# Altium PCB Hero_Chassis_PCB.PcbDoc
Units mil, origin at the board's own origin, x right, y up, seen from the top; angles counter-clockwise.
Board outline 2952.76 x 1771.65 mil, 2 copper layers (Top Layer, Bottom Layer); 15 components, 15 nets, 51 pads, 0 vias.
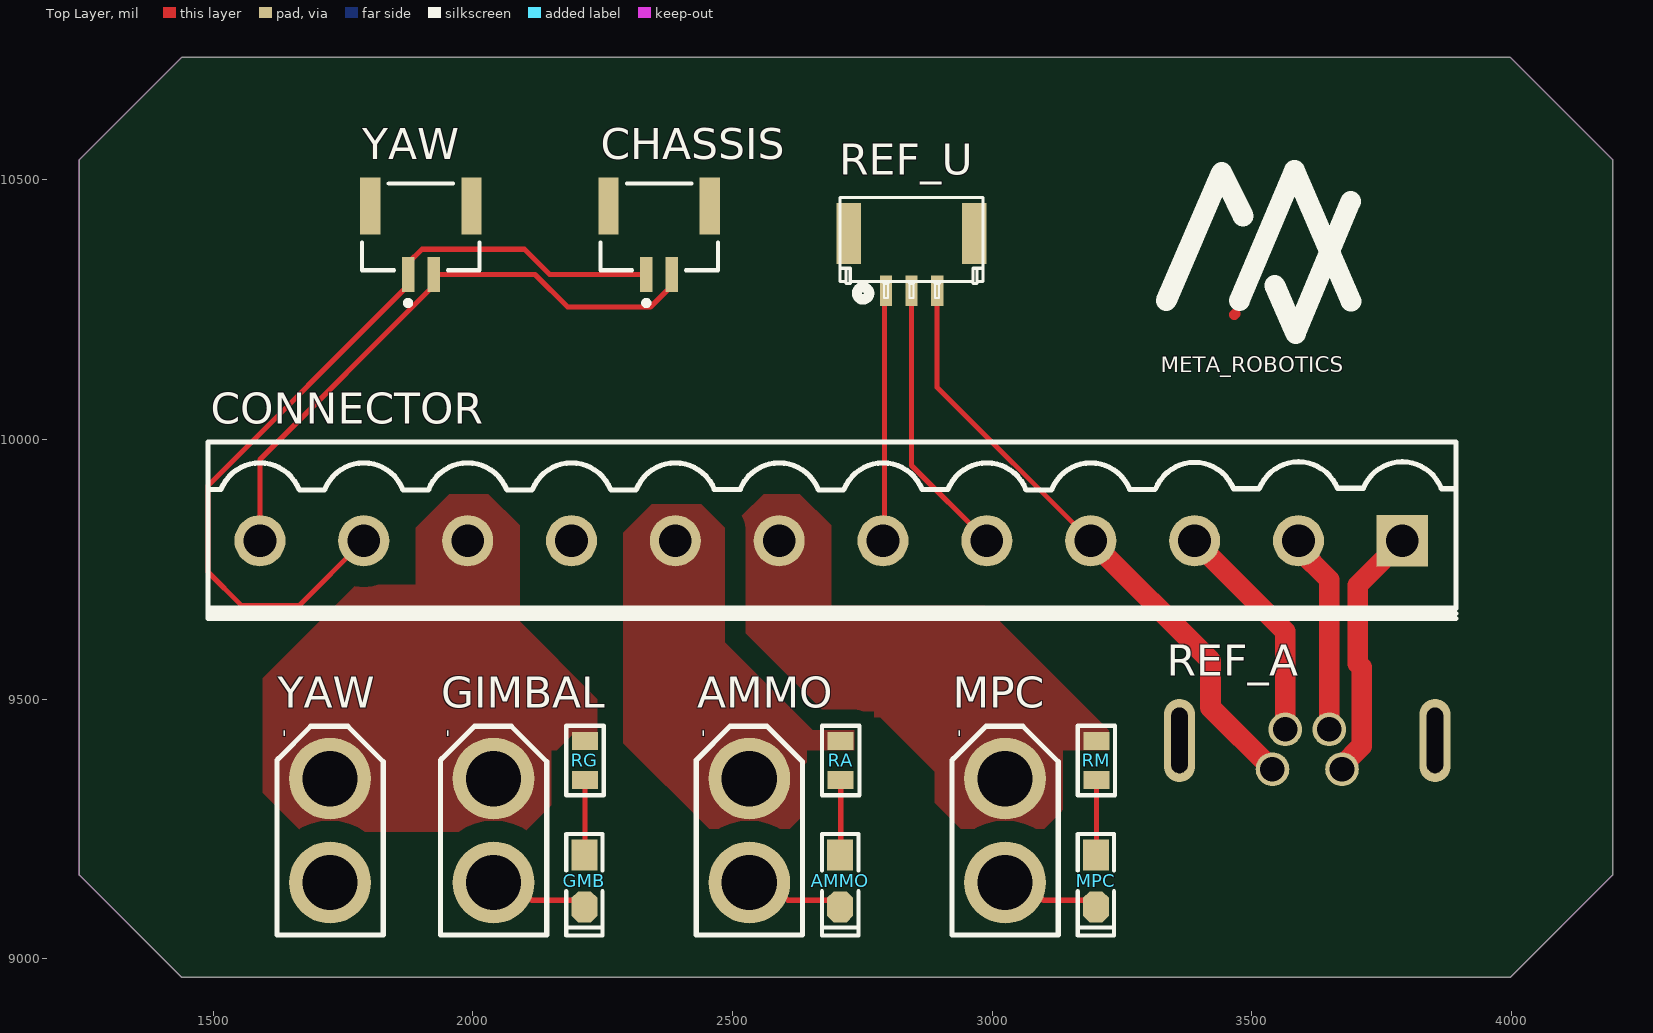
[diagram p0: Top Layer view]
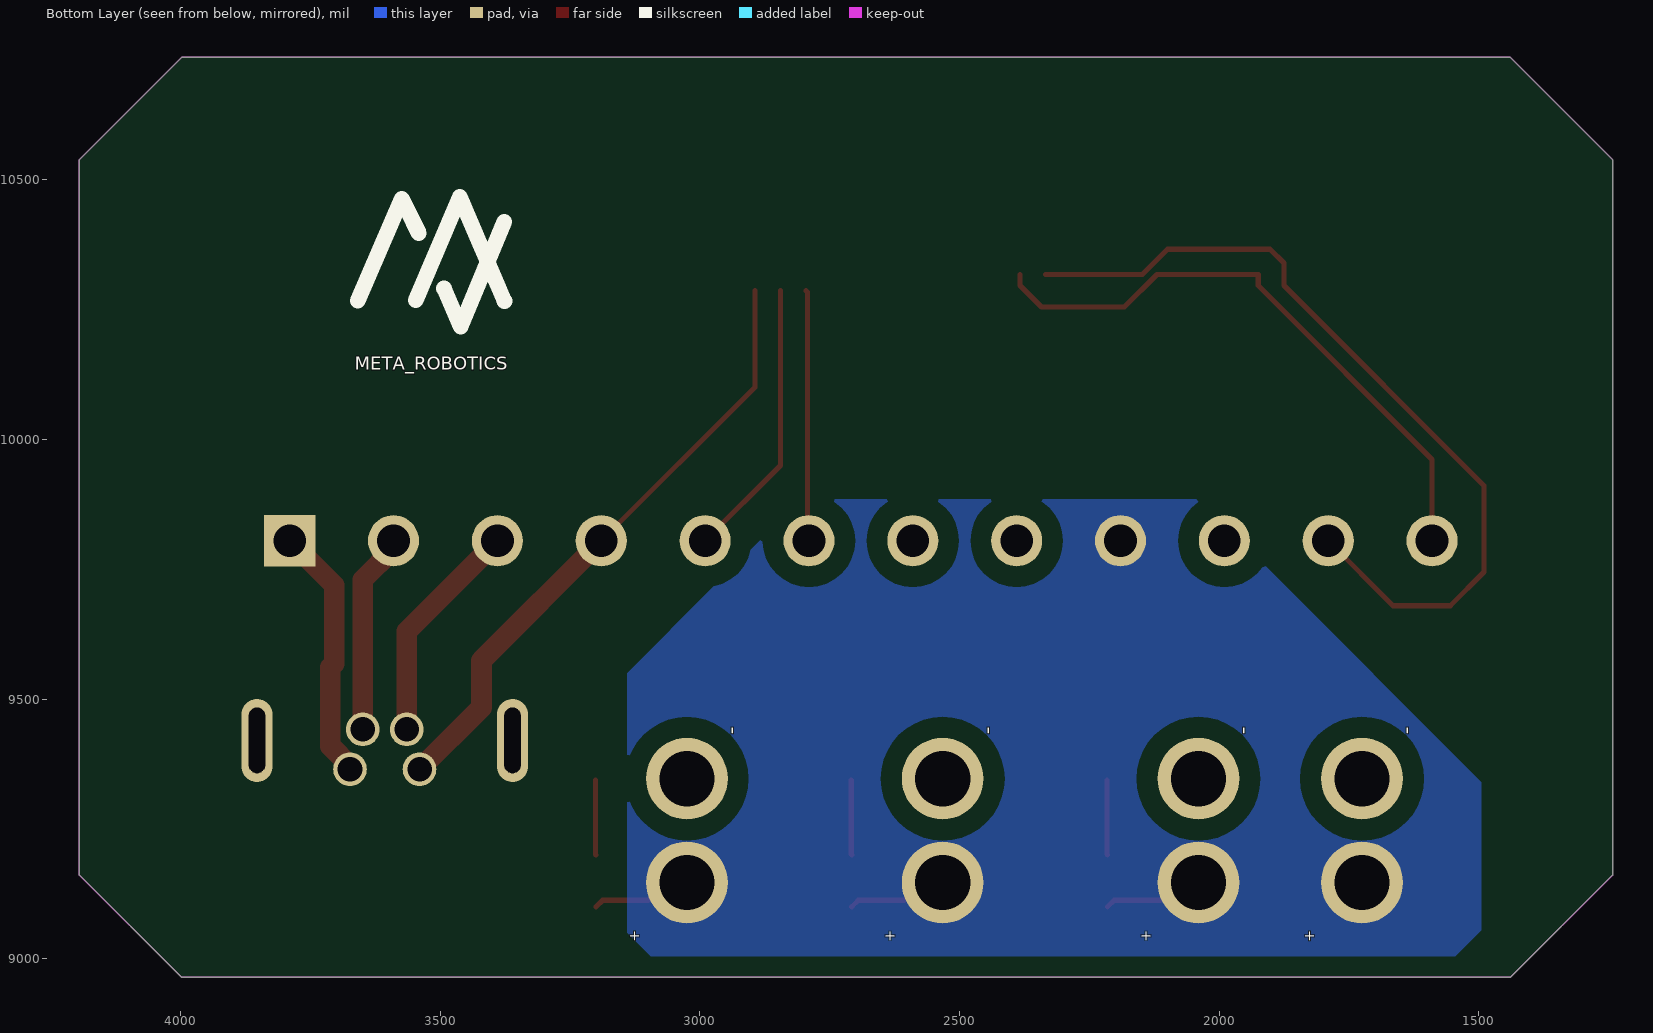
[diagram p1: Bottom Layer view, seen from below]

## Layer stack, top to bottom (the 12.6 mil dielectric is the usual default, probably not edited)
Top Solder: solder mask 0.4, Solder Resist, Dk 3.5
Top Layer: signal copper 1.4
Dielectric 1: dielectric 12.6, FR-4, Dk 4.8
Bottom Layer: signal copper 1.4
Bottom Solder: solder mask 0.4, Solder Resist, Dk 3.5

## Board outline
1439.14,8964.25 1242.29,9161.1 1242.29,10539.05 1439.14,10735.9 3998.19,10735.9 4195.04,10539.05 4195.04,9161.1 3998.19,8964.25

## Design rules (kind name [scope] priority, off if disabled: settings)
Clearance [InPolygon] p1: gap=40 ignorepadtopadclearanceinfootprint=FALSE
PlaneClearance [All] p1: clearance=40
PlaneConnect [All] p1: planeconnectstyle=Direct reliefexpansion=20 reliefentries=4 reliefconductorwidth=10 reliefairgap=10
PolygonConnect [All] p1: connectstyle=Direct reliefconductorwidth=10 reliefentries=4 polygonreliefangle="90 Angle" airgapwidth=10
RoutingVias [All] p1: holewidth=28 width=50 viastyle="Through Hole" minholewidth=28 minwidth=50 maxholewidth=28 maxwidth=50
SolderMaskExpansion [All] p1: expansion=4 istentingtop=FALSE
Width [All] p1: maxlimit=80 minlimit=10 preferedwidth=40
28 further rules are at their usual default settings.

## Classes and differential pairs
component class Schematic: AMMO CHASSIS CONNECTOR GIMBAL GMB MPC RA REF_A REF_U RG RM YAW

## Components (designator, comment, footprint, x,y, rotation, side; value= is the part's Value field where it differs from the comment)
AMMO "XT PLUGIN" XT30-M 2532.5,9246.79 r90 top
AMMO "红色" "LED 0805G" 2707.5,9150 r270 top
CHASSIS "CAN1" JST-BM02B-GHS-TBT_V 2358.72,10383.95 r0 top
CONNECTOR "HDR-1X12" KF2EDGK5.08-LI-12P 2690,9805 r180 top
GIMBAL "XT PLUGIN" XT30-M 2040,9246.79 r90 top
GMB "红色" "LED 0805G" 2215.01,9150 r270 top
MPC "XT PLUGIN" XT30-M 3024.99,9246.79 r90 top
MPC "红色" "LED 0805G" 3200,9150 r270 top
RA "10K" "R 0805_L" 2708.51,9381.86 r270 top
REF_A "Referee_Air" "M8 Connector" 3606.93,9402.4 r0 top
REF_U "gh1.25_3p" GH1.25-LS-3P 2845,10385 r180 top
RG "10K" "R 0805_L" 2216.01,9381.86 r270 top
RM "10K" "R 0805_L" 3201,9381.86 r270 top
YAW "CAN1" JST-BM02B-GHS-TBT_V 1900,10383.95 r0 top
YAW "XT PLUGIN" XT30-M 1725,9246.79 r90 top

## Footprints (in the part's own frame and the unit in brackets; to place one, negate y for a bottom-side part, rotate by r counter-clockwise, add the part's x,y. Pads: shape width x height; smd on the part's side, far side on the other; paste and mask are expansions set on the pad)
GH1.25-LS-3P [mm] "A1257WR-S-3P"
  rect 1.2x3 smd: 0(-3.075,-0.3) 0(3.075,-0.3)
  rect 0.6x1.5 smd: 1(1.25,2.5) 2(0,2.5) 3(-1.25,2.5)
  silkscreen extent -3.5,-2.05 3.5,2.93, body extent -3.5,-2.15 3.5,2.25, height 4.2
JST-BM02B-GHS-TBT_V [mm] "Connector, 2-Leads, Body 5.75x4.25mm, Pitch 1.25mm"
  rect 0.6x1.7 smd: 1(-0.625,-1.675) 2(0.625,-1.675)
  rect 1x2.8 smd: MP1(-2.475,1.675) MP2(2.475,1.675)
  silkscreen extent -2.88,-3.2 2.88,2.78, body extent -2.88,-2.17 2.87,2.78, height 4.21
KF2EDGK5.08-LI-12P [mm] "立插端子"
  rect 2.5x2.5 hole 1.6: 1(-27.94,0)
  round 2.5 hole 1.6: 2(-22.86,0) 3(-17.78,0) 4(-12.7,0) 5(-7.62,0) 6(-2.54,0) 7(2.54,0) 8(7.62,0) 9(12.7,0) 10(17.78,0) 11(22.86,0) 12(27.94,0)
  silkscreen extent -30.56,-4.83 30.48,3.81, body extent -30.48,-4.75 30.48,3.75, height 11.25
"LED 0805G" [mil] "绿色0805LED                              淘宝ID:黄晶宝石"
  rect 60x50 smd: 1(-50,0)
  oct 60x50 smd: 2(50,0)
  silkscreen extent -90,-35 105,35, body extent -39,-25 39,25, height 32
"M8 Connector" [mm]
  round 1.65 hole 1.2: 0(-1.075,1) 1(1.075,1) 2(-1.7,-0.95) 3(1.7,-0.95)
  oval 1.524x4.064 hole 0.8 slot 3.2 at 90 deg: 4(-6.25,0.46) 5(6.25,0.46)
  body extent -6.25,-19.34 6.25,1.96, height 11.3
"R 0805_L" [mil] "1/8W贴片电阻"
  rect 35x50 smd: 1(-37.4,0) 2(37.4,0)
  silkscreen extent -67,-36 67,36, body extent -39,-25 39,25, height 20
XT30-M [mm]
  round 4 hole 2.7: 1(-2.54,0) 2(2.54,0)
  silkscreen extent -5.1,-2.6 5.11,2.6, body extent -5.18,-2.8 5.02,2.8, height 10.66

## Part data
AMMO GMB MPC: library part LED-SMD, "贴片LED"
CHASSIS YAW: library part CMP-2000-05957-1, "Disconnectable Crimp Style Connector, Pitch 1.25 mm, 1 x 2 Position, Height 4.05 mm, -25 to 85 degC, RoHS, Tape and Reel", Color=Natural, Manufacturer=JST-Sales-America-Inc., Package Description="Disconnectable Crimp Style Connector, Pitch 1.25 mm, 1 x 2 Position, Height 4.05 mm", Package Reference=BM02B-GHS-TBT
CONNECTOR: library part "Header 12", "12P接插件"
RA RG RM: library part R, "贴片电阻"

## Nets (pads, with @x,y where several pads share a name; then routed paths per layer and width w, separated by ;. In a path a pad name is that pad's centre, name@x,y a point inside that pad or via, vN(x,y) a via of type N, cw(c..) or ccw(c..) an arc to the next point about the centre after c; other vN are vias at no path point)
AMMO_DC: AMMO.2@2532.5,9346.79 CONNECTOR.8 RA.1
CAN2_H: CHASSIS.2 CONNECTOR.12 YAW.2@1924.61,10318.01 | length 1175.2
  Top Layer w10: CONNECTOR.12 1590,9961.75 1924.61,10296.35 1924.61,10318.01 2119.73,10318.01 2182.74,10255 2341.97,10255 2383.33,10296.35 CHASSIS.2
CAN2_L: CHASSIS.1 CONNECTOR.11 YAW.1@1875.39,10318.01 | length 1622.9
  Top Layer w10: CONNECTOR.11 1665,9680 1555,9680 1490,9745 1490,9910.96 1875.39,10296.35 1875.39,10318.01 1875.39,10339.66 1902.2,10366.47 2099.55,10366.47 2148.02,10318.01 CHASSIS.1
GIMBAL_DC: CONNECTOR.10 GIMBAL.2 RG.1 YAW.2@1725,9346.79
GND: AMMO.1@2532.5,9146.79 AMMO.2@2707.5,9100 CONNECTOR.9 GIMBAL.1 GMB.2 MPC.1@3024.99,9146.79 MPC.2@3200,9100 YAW.1@1725,9146.79 | length 583.2
  Top Layer w10: GIMBAL.1 2079.91,9146.79 2114.2,9112.5 2202.51,9112.5 GMB.2 ; AMMO.1@2532.5,9146.79 2572.4,9146.79 2606.69,9112.5 2695,9112.5 AMMO.2@2707.5,9100 ; MPC.1@3024.99,9146.79 3064.9,9146.79 3099.19,9112.5 3187.5,9112.5 MPC.2@3200,9100
MPC_DC: CONNECTOR.7 MPC.2@3024.99,9346.79 RM.1
NetAMMO_1: AMMO.1@2707.5,9200 RA.2 | length 144.9
  Top Layer w10: AMMO.1@2707.5,9200 2708.5,9201 RA.2
NetGMB_1: GMB.1 RG.2 | length 144.9
  Top Layer w10: GMB.1 2216.01,9201 RG.2
NetMPC_1: MPC.1@3200,9200 RM.2 | length 144.9
  Top Layer w10: MPC.1@3200,9200 3201,9201 RM.2
REFEREE_A1: CONNECTOR.3 REF_A.0 | length 435.6
  Top Layer w40: CONNECTOR.3 3564.61,9630.39 REF_A.0
REFEREE_A2: CONNECTOR.2 REF_A.1 | length 387.8
  Top Layer w40: CONNECTOR.2 3590,9789.19 3649.25,9729.94 REF_A.1
REFEREE_A3: CONNECTOR.1 REF_A.3 | length 494.3
  Top Layer w40: REF_A.3 3673.86,9371.75 3711.73,9409.63 3711.73,9560.67 3704.23,9568.18 3704.23,9719.22 CONNECTOR.1
REFEREE_GND: CONNECTOR.4 REF_A.2 REF_U.3 | length 1189.1
  Top Layer w10: REF_U.3 2894.21,10100.79 CONNECTOR.4
  Top Layer w40: CONNECTOR.4 3420.87,9574.13 3420.87,9484.13 REF_A.2
REFEREE_UR: CONNECTOR.5 REF_U.2 | length 541.6
  Top Layer w10: REF_U.2 2845,9950 CONNECTOR.5
REFEREE_UT: CONNECTOR.6 REF_U.1 | length 484
  Top Layer w10: CONNECTOR.6 2792.89,9807.89 2792.89,10283.68 REF_U.1
pads on no net: CHASSIS.MP1 CHASSIS.MP2 REF_A.4 REF_A.5 REF_U.0 YAW.MP1 YAW.MP2
copper on no net: | length 2.6
  Top Layer w20: 3466.57,10240.39 3468.39,10242.2

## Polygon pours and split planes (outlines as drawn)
MPC_DC on Top Layer "MPC_DC_L01_P004" (solid, pour order 4): 2500,9620 2655,9465 2785,9465 2890,9360 2890,9300 2940,9250 3100,9250 3145,9295 3145,9400 3225,9400 3225,9440 2985,9680 2690,9680 2690,9835 2630,9895 2560,9895 2500,9835
AMMO_DC on Top Layer "AMMO_DC_L01_P003" (solid, pour order 3): 2345,9875 2440,9875 2485,9830 2485,9610 2655,9440 2735,9440 2735,9400 2665,9400 2635,9370 2635,9275 2610,9250 2455,9250 2290,9415 2290,9820
GIMBAL_DC on Top Layer "GIMBAL_DC_L01_P000" (solid, pour order 0): 1955,9895 1890,9830 1890,9720 1775,9720 1595,9540 1595,9320 1670,9245 2100,9245 2155,9300 2155,9395 2195,9435 2240,9435 2240,9500 2090,9650 2090,9835 2030,9895
GND on Bottom Layer "GND" (solid, pour order 5): 2040,9885 1495,9340 1495,9055 1565,8985 3075,8985 3140,9050 3140,9550 2805,9885

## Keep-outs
Keep-Out Layer:
  the board outline again, w0.5

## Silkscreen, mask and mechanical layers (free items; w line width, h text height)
Top Overlay:
  lines w40: 3335.34,10267.42 3442.15,10514.39 3483.19,10430.63 ; 3476.43,10267.91 3582.28,10518.6 3691.11,10266.31 ; 3544.35,10296.74 3584.6,10204.3 3690.53,10458.43
  text "META_ROBOTICS" at 3325,10130 h30
Bottom Overlay:
  lines w30: 3376.36,10266.7 3462.8,10467.09 3546.88,10267.97 ; 3376.82,10419.3 3460.96,10217.44 3492.93,10290.87 ; 3541.51,10397.22 3574.11,10463.74 3658.95,10267.58
  text "META_ROBOTICS" at 3665,10134.17 h25
Mechanical 1:
  the board outline again, w0.5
